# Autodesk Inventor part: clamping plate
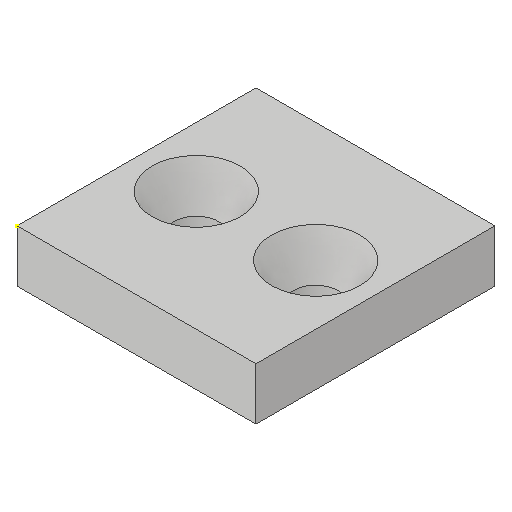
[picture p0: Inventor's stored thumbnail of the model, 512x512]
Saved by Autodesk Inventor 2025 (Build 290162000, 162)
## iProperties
Created: 2016-03
Part Number: clamping plate
Material: Generic
Document SubType Name: Modeling
Designer: Sandeep
Density: 1 g/cm^3
Appearance: Default
Mass: 6.41192 g
Surface Area: 30.6752 cm^2
Volume: 6.41192 cm^3
Author: Sandeep
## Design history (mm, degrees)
sketch "Sketch1"
  geometry: L1 (0, 0)-(32, 0); L2 (32, 0)-(32, 32); L3 (32, 32)-(0, 32); L4 (0, 32)-(0, 0)
  constraints: 8 end point, 2 parallel, 1 horizontal, 1 perpendicular
  dimensions: "d0" = 32 distance between parallel lines of L1 L3; "d1" = 32 distance of L2.end L3.end
extrude "Extrusion1" new body sketch "Sketch1" distance "d2" = 7; taper "d3" = 0 deg
hole "Hole2" diameter "d15" = 6; stored, may be unused: countersink angle "d19" = 60 deg, drill point angle "d21" = 118 deg; dims "d13" = 8, "d14" = 16, "d16" = 6, "d17" = 11.78, "d18" = 2, "d20" = 8
hole "Hole3" diameter "d24" = 6; stored, may be unused: countersink angle "d28" = 60 deg, drill point angle "d30" = 118 deg; dims "d22" = 8, "d23" = 16, "d25" = 6, "d26" = 11.78, "d27" = 2, "d29" = 8
body "Solid1"
sketch "Sketch2"
  geometry: 1 further point
sketch "Sketch3"
  geometry: 1 further point
sketch "Sketch4"
  geometry: 1 further point
